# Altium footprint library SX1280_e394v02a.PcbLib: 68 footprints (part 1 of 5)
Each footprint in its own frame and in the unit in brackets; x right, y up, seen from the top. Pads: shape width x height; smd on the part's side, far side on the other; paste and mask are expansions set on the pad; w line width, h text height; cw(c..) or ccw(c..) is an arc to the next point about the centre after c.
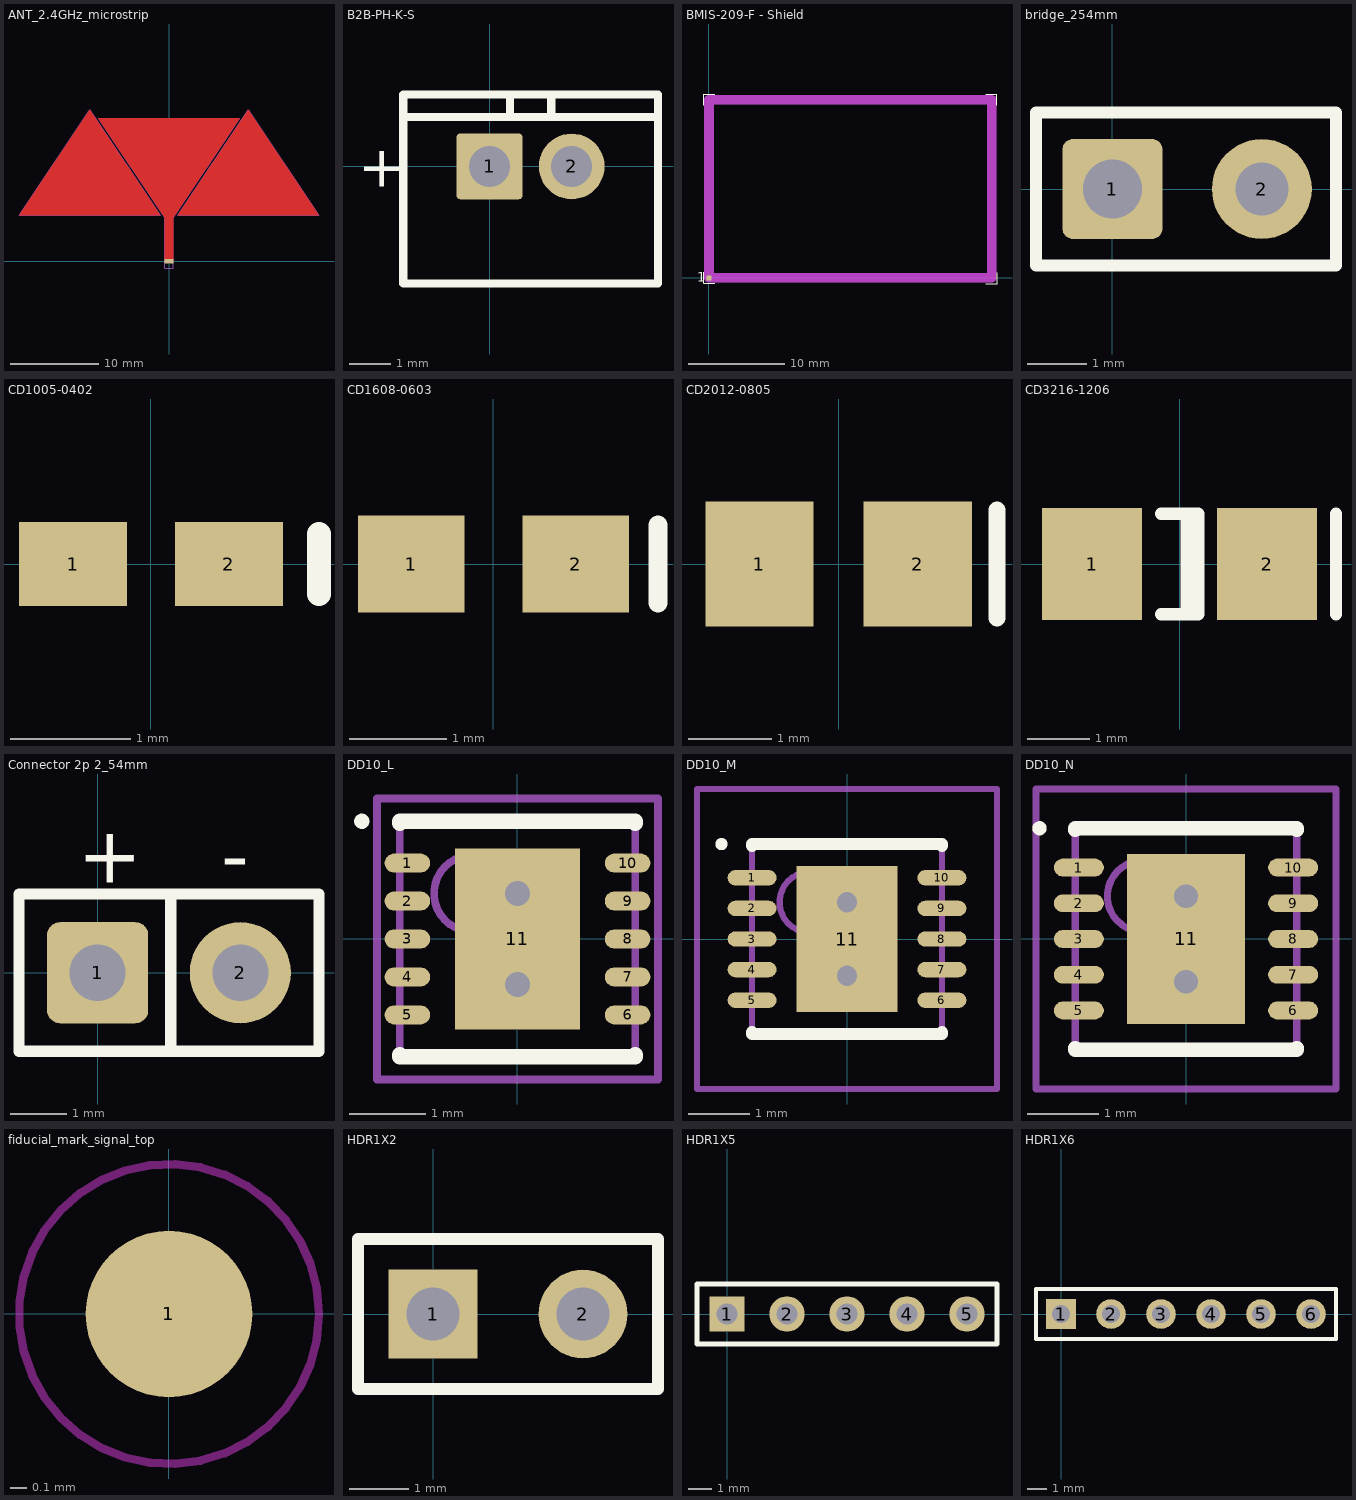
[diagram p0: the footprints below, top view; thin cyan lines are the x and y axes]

## ANT_2.4GHz_microstrip [mm] "Antenna 2.4 GHz ISM band - Microstrip"
height 0.2
pads (1):
  rect 1x0.5 smd paste-1 mask-1: 1(0,0)
Top Layer:
  region: -17,5.2 -1,5.2 -9,17.2
  region: 1,5.2 17,5.2 9,17.2
  region: 8,16.2 -8,16.2 -0.5,4.95 -0.5,0.2 0.5,0.2 0.5,4.95
Mechanical 15:
  lines w0.1: -0.5,-0.8 0.5,-0.8 ; -0.5,-0.8 -0.5,0.15 0.5,0.15 0.5,-0.8 ; -0.5,-0.8 -0.5,4.95 -8,16.2 8,16.2 0.5,4.95 0.5,-0.8 ; -17,5.2 -9,17.2 -1,5.2 -17,5.2 ; 1,5.2 17,5.2 9,17.2 1,5.2
3D body: height 2.95, standoff 0, extent -0.5,-0.25 0.5,0.2

## B2B-PH-K-S [mm] "B2B-PH-K-S; JST; Battery Connector; Header; 2 Position"
pads (2):
  rrect10% 1.6x1.6 hole 1: 1(0,0)
  round 1.6 hole 1: 2(2,0)
Top Overlay:
  lines w0.2: -2.1,1.2 4.1,1.2 ; 0.5,1.2 0.5,1.75 ; 1.5,1.2 1.5,1.75 ; -2.1,-2.85 4.1,-2.85 4.1,1.75 -2.1,1.75 -2.1,-2.85
  text "+" at -3.2,-0.5 h1
3D body: height 2.95, standoff 0, extent -2.1,-2.8 4.1,1.7

## BMIS-209-F - Shield [mm] "BMIS-209-F EMI Gasket - modif SolderMask - Standard Surface Mount Shields -  Laird Technologies"
height 6.5
pads (1):
  rect 0.5x0.5 smd paste-1 mask+0.05: 1(0,0)
Top Overlay:
  lines w0.1: -0.55,0.6 -0.55,-0.55 0.6,-0.55 ; -0.55,18 -0.55,19.15 0.6,19.15 ; 28.9,-0.6 30.05,-0.6 30.05,0.55 ; 28.9,19.15 30.05,19.15 30.05,18
  text "1" at -1.25,-0.4 h1
Top Paste:
  region: 4.35,0.6 4.35,-0.4 -0.4,-0.4 -0.4,0.6
  region: 7.1,0.375 10.3,0.375 10.3,-0.4 7.1,-0.4
  region: 13.1,0.6 16.35,0.6 16.35,-0.4 13.1,-0.4
  region: 19.1,0.6 22.3,0.6 22.3,-0.4 19.1,-0.4
  region: 25.1,0.55 29.9,0.55 29.9,-0.45 25.1,-0.45
  region: -0.4,4.6 0.6,4.6 0.6,-0.4 -0.4,-0.4
  region: -0.4,10.9 0.6,10.9 0.6,7.7 -0.4,7.7
  region: -0.4,13.7 -0.4,19 0.6,19 0.6,13.7
  region: 28.9,13.65 28.9,18.95 29.9,18.95 29.9,13.65
  region: 28.9,10.85 29.9,10.85 29.9,7.65 28.9,7.65
  region: 28.9,4.85 29.9,4.85 29.9,-0.45 28.9,-0.45
  region: 25.1,19 29.9,19 29.9,18 25.1,18
  region: 19.1,19 22.3,19 22.3,18 19.1,18
  region: 13.1,19 16.35,19 16.35,18 13.1,18
  region: 7.1,19 10.3,19 10.3,18 7.1,18
  region: 4.35,19 4.35,18 -0.4,18 -0.4,19
Top Solder:
  region: 4.35,18 -0.4,18 -0.4,19 4.35,19
  region: 10.3,18 7.1,18 7.1,19 10.3,19
  region: 16.35,18 13.1,18 13.1,19 16.35,19
  region: 29.9,18 25.1,18 25.1,19 29.9,19
  region: 22.3,18 19.1,18 19.1,19 22.3,19
  region: 22.3,-0.4 19.1,-0.4 19.1,0.6 22.3,0.6
  region: 29.9,-0.45 25.1,-0.45 25.1,0.55 29.9,0.55
  region: 16.35,-0.4 13.1,-0.4 13.1,0.6 16.35,0.6
  region: 10.3,-0.4 7.1,-0.4 7.1,0.375 10.3,0.375
  region: 4.35,-0.4 -0.4,-0.4 -0.4,0.6 4.35,0.6
  region: -0.4,13.7 -0.4,19 0.6,19 0.6,13.7
  region: -0.4,7.7 -0.4,10.9 0.6,10.9 0.6,7.7
  region: -0.4,-0.4 -0.4,4.6 0.6,4.6 0.6,-0.4
  region: 28.9,-0.45 28.9,4.85 29.9,4.85 29.9,-0.45
  region: 28.9,7.65 28.9,10.85 29.9,10.85 29.9,7.65
  region: 28.9,13.65 28.9,18.95 29.9,18.95 29.9,13.65
Mechanical 15 keep-out:
  lines w1: 0,0 0,18.6 29.5,18.6 29.5,0 0,0
3D body: height 0.8, standoff 0.2, extent -0.3,-0.3 0.3,0.3

## bridge_254mm [mm] "Generic Bridge 2.54mm, 2 Leads 0.9mm;"
height 1
pads (2):
  rrect20% 1.7x1.7 hole 1 paste+0 mask+0.05: 1(0,0)
  round 1.7 hole 0.9 paste+0 mask+0.05: 2(2.54,0)
Top Overlay:
  lines w0.2: -1.3,-1.3 3.8,-1.3 3.8,1.3 -1.3,1.3 -1.3,-1.3

## CD1005-0402 [mm] "Chip Diode; Body 1.0 x 0.5 mm (LxW typ)"
height 0.6
pads (2):
  rect 0.9x0.7 smd mask+0.05: 1(-0.65,0) 2(0.65,0)
Top Overlay:
  lines w0.2: 1.4,-0.25 1.4,0.25

## CD1608-0603 [mm] "Chip Diode; Body 1.6 x 0.8 mm (LxW typ)"
height 0.85
pads (2):
  rect 1.1x1 smd mask+0.05: 1(-0.85,0) 2(0.85,0)
Top Overlay:
  lines w0.2: 1.7,-0.4 1.7,0.4

## CD2012-0805 [mm] "Chip Diode; Body 2.0 x 1.3 mm (LxW typ)"
height 1.1
pads (2):
  rect 1.3x1.5 smd mask+0.05: 1(-0.95,0) 2(0.95,0)
Top Overlay:
  lines w0.2: 1.9,-0.65 1.9,0.65

## CD3216-1206 [mm] "Chip Diode; Body 3.2 x 1.6 mm (LxW typ)"
height 1.35
pads (2):
  rect 1.6x1.8 smd mask+0.05: 1(-1.4,0) 2(1.4,0)
Top Overlay:
  lines w0.2: -0.3,-0.8 0.3,-0.8 0.3,0.8 -0.3,0.8 ; 0.11,-0.8 0.11,0.8 ; 2.5,-0.8 2.5,0.8

## Connector 2p 2_54mm [mm] "Generic connector 2.54mm, 2 Leads 1mm;"
height 1
pads (2):
  rrect25% 1.8x1.8 hole 1 paste+0 mask+0.05: 1(0,0)
  round 1.8 hole 1 paste+0 mask+0.05: 2(2.54,0)
Top Overlay:
  lines w0.2: 1.3,-1.4 1.3,1.4 ; -1.4,-1.4 3.94,-1.4 3.94,1.4 -1.4,1.4 -1.4,-1.4
  text "+" at -0.35,1.6 h1
  text "-" at 2.2,1.6 h1

## DD10_L [mm] "SON, 10-Leads, Body 3x3 mm, Pitch 0.5mm, IPC High Density"
height 0.8
pads (11):
  oval 0.6x0.25 smd: 1(-1.45,1) 2(-1.45,0.5) 3(-1.45,0) 4(-1.45,-0.5) 5(-1.45,-1) 6(1.45,-1) 7(1.45,-0.5) 8(1.45,0) 9(1.45,0.5) 10(1.45,1)
  rect 1.65x2.38 smd: 11(0,0)
via 0,-0.6 diameter 0.66 hole 0.33
via 0,0.6 diameter 0.66 hole 0.33
Top Overlay:
  circle w0.1: c-2.05,1.55 r0.05
  lines w0.2: -1.55,-1.525 -1.55,-1.55 1.55,-1.55 1.55,-1.525 ; -1.55,1.525 -1.55,1.55 1.55,1.55 1.55,1.525
Mechanical 13:
  circle w0.1: c-0.6,0.6 r0.5
  lines w0.1: -1.55,-1.55 -1.55,1.55 1.55,1.55 1.55,-1.55 -1.55,-1.55
Mechanical 15:
  lines w0.1: -0.5,0 0.5,0 ; 0,-0.5 0,0.5 ; -1.85,-1.85 -1.85,1.85 1.85,1.85 1.85,-1.85 -1.85,-1.85
3D body: height 0.8, standoff 0, extent -1.55,-1.55 1.55,1.55

## DD10_M [mm] "SON, 10-Leads, Body 3x3 mm, Pitch 0.5mm, IPC Low Density"
height 0.8
pads (11):
  oval 0.8x0.25 smd: 1(-1.55,1) 2(-1.55,0.5) 3(-1.55,0) 4(-1.55,-0.5) 5(-1.55,-1) 6(1.55,-1) 7(1.55,-0.5) 8(1.55,0) 9(1.55,0.5) 10(1.55,1)
  rect 1.65x2.38 smd: 11(0,0)
via 0,-0.6 diameter 0.66 hole 0.33
via 0,0.6 diameter 0.66 hole 0.33
Top Overlay:
  circle w0.1: c-2.05,1.55 r0.05
  lines w0.2: -1.55,-1.525 -1.55,-1.55 1.55,-1.55 1.55,-1.525 ; -1.55,1.525 -1.55,1.55 1.55,1.55 1.55,1.525
Mechanical 13:
  circle w0.1: c-0.6,0.6 r0.5
  lines w0.1: -1.55,-1.55 -1.55,1.55 1.55,1.55 1.55,-1.55 -1.55,-1.55
Mechanical 15:
  lines w0.1: -0.5,0 0.5,0 ; 0,-0.5 0,0.5 ; -2.45,-2.45 -2.45,2.45 2.45,2.45 2.45,-2.45 -2.45,-2.45
3D body: height 0.8, standoff 0, extent -1.55,-1.55 1.55,1.55

## DD10_N [mm] "SON, 10-Leads, Body 3x3 mm, Pitch 0.5mm, IPC Medium Density"
height 0.8
pads (11):
  oval 0.7x0.25 smd: 1(-1.5,1) 2(-1.5,0.5) 3(-1.5,0) 4(-1.5,-0.5) 5(-1.5,-1) 6(1.5,-1) 7(1.5,-0.5) 8(1.5,0) 9(1.5,0.5) 10(1.5,1)
  rect 1.65x2.38 smd: 11(0,0)
via 0,-0.6 diameter 0.66 hole 0.33
via 0,0.6 diameter 0.66 hole 0.33
Top Overlay:
  circle w0.1: c-2.05,1.55 r0.05
  lines w0.2: -1.55,-1.525 -1.55,-1.55 1.55,-1.55 1.55,-1.525 ; -1.55,1.525 -1.55,1.55 1.55,1.55 1.55,1.525
Mechanical 13:
  circle w0.1: c-0.6,0.6 r0.5
  lines w0.1: -1.55,-1.55 -1.55,1.55 1.55,1.55 1.55,-1.55 -1.55,-1.55
Mechanical 15:
  lines w0.1: -0.5,0 0.5,0 ; 0,-0.5 0,0.5 ; -2.1,-2.1 -2.1,2.1 2.1,2.1 2.1,-2.1 -2.1,-2.1
3D body: height 0.8, standoff 0, extent -1.55,-1.55 1.55,1.55

## fiducial_mark_signal_top [mm] "Fiducial mark for automatic assembly"
height 1
pads (1):
  round 1 smd paste-2 mask+0.5: 1(0,0)
Top Layer keep-out:
  circle w0.05: c0,0 r0.9

## HDR1X2 [mm] "Connector; Header; 2 Position"
pads (2):
  rect 1.5x1.5 hole 0.9: 1(0,0)
  round 1.5 hole 0.9: 2(2.54,0)
Top Overlay:
  lines w0.2: -1.27,-1.27 3.81,-1.27 3.81,1.27 -1.27,1.27 -1.27,-1.27

## HDR1X5 [mm] "Connector; Header; 5 Position"
pads (5):
  rect 1.5x1.5 hole 0.9: 1(0,0)
  round 1.5 hole 0.9: 2(2.54,0) 3(5.08,0) 4(7.62,0) 5(10.16,0)
Top Overlay:
  lines w0.2: -1.27,-1.27 -1.27,1.27 11.43,1.27 11.43,-1.27 -1.27,-1.27

## HDR1X6 [mm] "Connector; Header; 6 Position"
pads (6):
  rect 1.5x1.5 hole 0.9: 1(0,0)
  round 1.5 hole 0.9: 2(2.54,0) 3(5.08,0) 4(7.62,0) 5(10.16,0) 6(12.7,0)
Top Overlay:
  lines w0.2: -1.27,-1.27 -1.27,1.27 13.97,1.27 13.97,-1.27 -1.27,-1.27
